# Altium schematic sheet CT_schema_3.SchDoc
size 176 x 147 mm
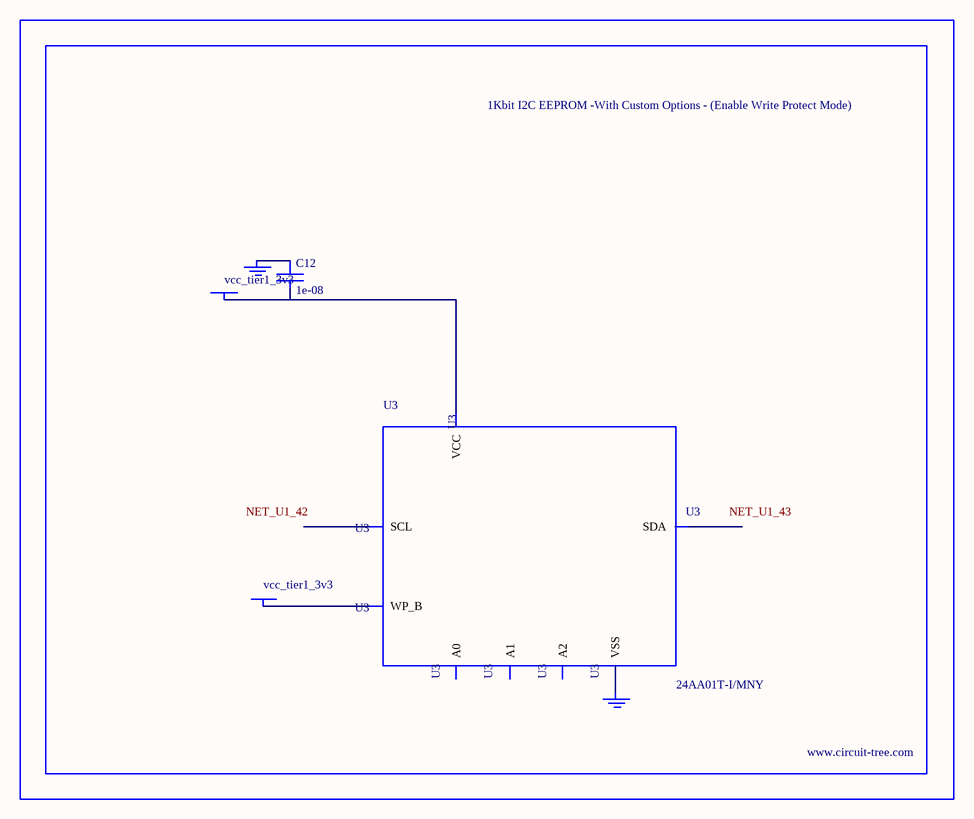
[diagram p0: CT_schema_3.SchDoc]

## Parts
BORDER2  (no value)
C12  1e-08  [C0402]
GND_INSTANCE_2_0  (no value)
GND_INSTANCE_2_1  (no value)
POWER_INSTANCE_2_0  vcc_tier1_3v3
POWER_INSTANCE_2_1  vcc_tier1_3v3
U3  24AA01T-I/MNY  [TDFN-8/6MM]

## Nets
NetC12_1: C12.1 GND_INSTANCE_2_0.0(GND)
NetC12_2: C12.2 POWER_INSTANCE_2_1.0(PWR) U3.8(VCC)
NetGND_INSTANCE_2_1_0: GND_INSTANCE_2_1.0(GND) U3.4(VSS)
NetPOWER_INSTANCE_2_0_0: POWER_INSTANCE_2_0.0(PWR) U3.7(WP_B)

Not connected (* = marked no-connect by the designer): U3 1(A0) 2(A1) 3(A2) 5(SDA) 6(SCL)

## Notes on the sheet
- Labels drawn without touching a wire or pin: NET_U1_42, NET_U1_43

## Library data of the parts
BORDER2 = BORDER_PAGE2
C12 = C0402C103K3RAC
GND_INSTANCE_2_0 GND_INSTANCE_2_1 = GND
POWER_INSTANCE_2_0 POWER_INSTANCE_2_1 = PWR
